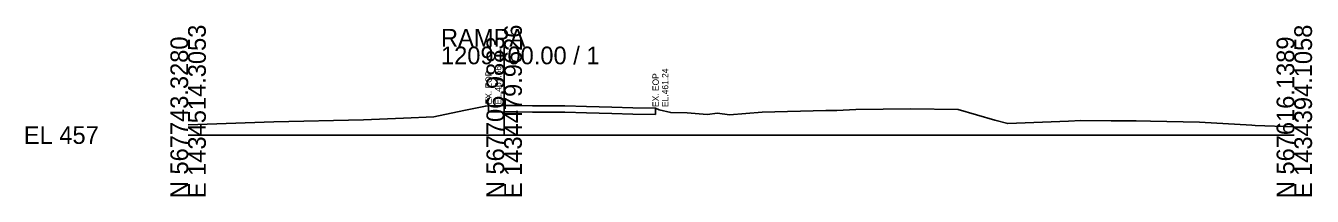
# Model space of a CAD drawing. Extents: x 1431908 to 1449087, y 567604 to 577825.
# Drawn here: x 1432908 to 1433111.5, y 575352.5 to 575379.5 of the extents above; entities that cross this region are included whole.
import ezdxf

# ---------------------------------------------------------------- set-up
doc = ezdxf.new("R2010")
doc.units = 0
for name, color, linetype in [('DESIGN - SHEET - Light Grid', 7, 'Continuous'), ('SURVEY - GROUND - Existing Pavement Layer', 7, 'Continuous'), ('SURVEY - GROUND - Existing Pavement Text', 7, 'Continuous'), ('SURVEY - GROUND - Top of Ground', 7, 'Continuous')]:
    doc.layers.add(name, color=color, linetype=linetype)

msp = doc.modelspace()

# ---------------------------------------------------------------- linework, layer by layer
at = {"layer": 'DESIGN - SHEET - Light Grid'}
for p, q in [((1432983.66, 575362.16), (1432983.66, 575376.17)), ((1432933.66, 575362.16), (1432983.66, 575362.16)), ((1432983.66, 575362.16), (1433108.66, 575362.16))]:
    msp.add_line(p, q, dxfattribs=at)
at = {"layer": 'SURVEY - GROUND - Existing Pavement Layer'}
for p, q in [((1432981.2, 575365.81), (1432981.2, 575366.81)), ((1433007.62, 575366.4), (1433007.62, 575365.4)), ((1432981.2, 575365.81), (1432983.66, 575365.82)), ((1432983.66, 575365.82), (1432984.53, 575365.83)), ((1432984.53, 575365.83), (1432985.53, 575365.82)), ((1432985.53, 575365.82), (1432988.14, 575365.81)), ((1432988.14, 575365.81), (1432993.23, 575365.78)), ((1432993.23, 575365.78), (1432996.68, 575365.68)), ((1432996.68, 575365.68), (1433000.67, 575365.58)), ((1433000.67, 575365.58), (1433004, 575365.49)), ((1433004, 575365.49), (1433007.62, 575365.4))]:
    msp.add_line(p, q, dxfattribs=at)
at = {"layer": 'SURVEY - GROUND - Top of Ground'}
msp.add_lwpolyline([(1432933.66, 575363.76), (1432947.22, 575364.27), (1432961.39, 575364.57), (1432967.71, 575364.83), (1432972.52, 575365.02), (1432977.3, 575366.05), (1432980.69, 575366.75), (1432981.2, 575366.81), (1432983.66, 575366.82), (1432984.53, 575366.83), (1432985.53, 575366.82), (1432988.14, 575366.81), (1432993.23, 575366.78), (1432996.68, 575366.68), (1433000.67, 575366.58), (1433004, 575366.49), (1433007.62, 575366.4), (1433008.19, 575366.14), (1433010.01, 575365.72), (1433012.61, 575365.69), (1433015.75, 575365.4), (1433017.41, 575365.64), (1433019.29, 575365.38), (1433024.47, 575365.78), (1433034.54, 575366.06), (1433036.27, 575366.07), (1433039.29, 575366.19), (1433047.95, 575366.33), (1433055.48, 575366.19), (1433061.27, 575364.54), (1433063.33, 575363.97), (1433072.92, 575364.36), (1433074.89, 575364.44), (1433079.68, 575364.41), (1433083.62, 575364.39), (1433085.89, 575364.35), (1433093.65, 575364.22), (1433101.92, 575363.72), (1433102.45, 575363.69), (1433108.66, 575363.47)], dxfattribs=at)

# ---------------------------------------------------------------- texts
at = {"layer": 'DESIGN - SHEET - Light Grid'}
for s, p in [('E 1434514.3053', (1432936.46, 575352.16)), ('E 1434479.9626', (1432986.46, 575352.16)), ('E 1434394.1058', (1433111.46, 575352.16)), ('N 567743.3280', (1432933.66, 575352.16)), ('N 567706.9883', (1432983.66, 575352.16)), ('N 567616.1389', (1433108.66, 575352.16))]:
    msp.add_text(s, height=2.8, rotation=90, dxfattribs=at).set_placement(p)
for s, p in [('RAMPA', (1432973.66, 575376.17)), ('1209+00.00 / 1', (1432973.66, 575373.37)), ('EL 457', (1432907.66, 575360.76))]:
    msp.add_text(s, height=2.8, dxfattribs=at).set_placement(p)
at = {"layer": 'SURVEY - GROUND - Existing Pavement Text'}
for s, p in [('EL.461.66', (1432983.2, 575367.01)), ('EL.461.24', (1433009.62, 575366.6)), ('EX. EOP', (1432981.7, 575367.01)), ('EX. EOP', (1433008.12, 575366.6))]:
    msp.add_text(s, height=1, rotation=90, dxfattribs=at).set_placement(p)

doc.saveas('drawing.dxf')
